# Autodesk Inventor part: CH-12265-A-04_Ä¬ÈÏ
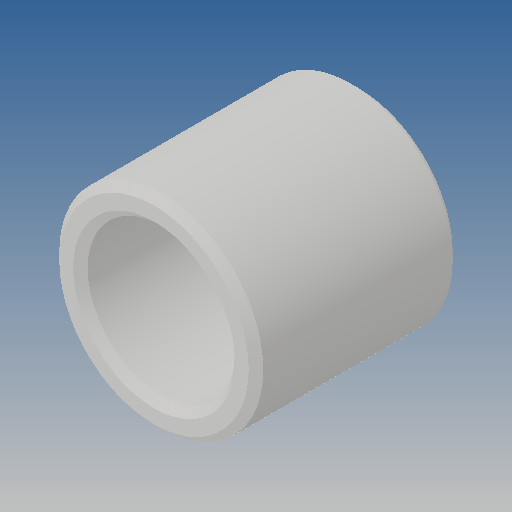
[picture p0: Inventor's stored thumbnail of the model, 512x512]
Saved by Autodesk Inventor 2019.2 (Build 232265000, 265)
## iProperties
Created: 2010-06
Part Number: CH-12265-A-04_Ä¬ÈÏ
Material: Ogólny
Document SubType Name: Modeling
Designer: CADENGINEERING4
Density: 1 g/cm^3
Appearance: Domyślna
Author: CADENGINEERING4
Revision Number: ÈÎºÎ
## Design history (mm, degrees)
feature "NONE"
node "Bryła1"
